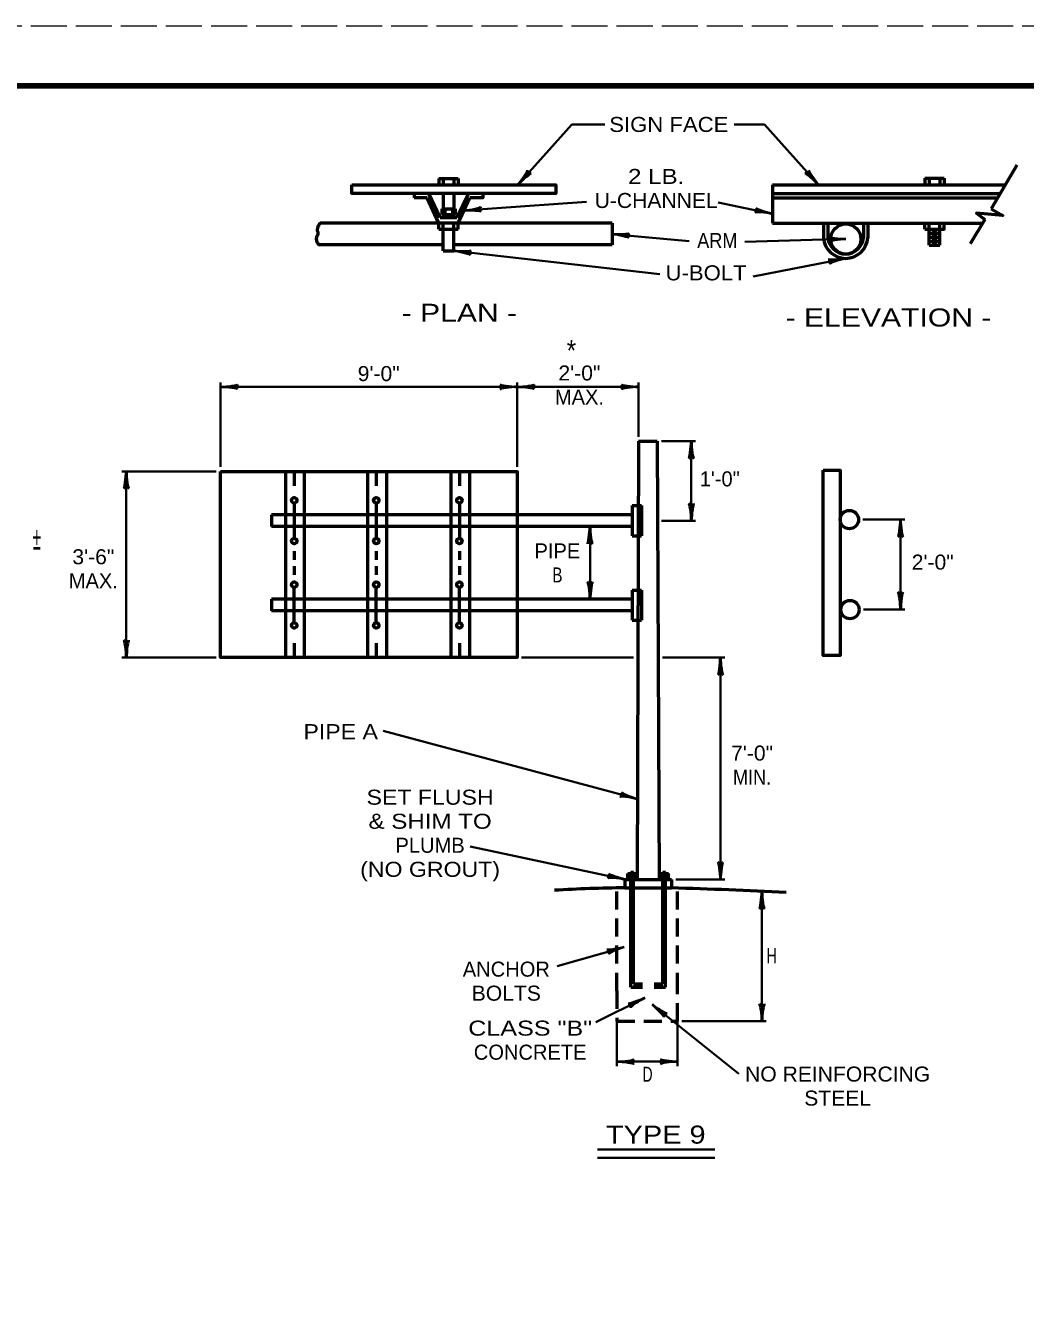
# Model space of a CAD drawing. Extents: x -209 to 471, y -242 to 199.
# Drawn here: x 135.5 to 301.8, y -15.9 to 198.5 of the extents above; entities that cross this region are included whole.
import ezdxf
from ezdxf.enums import TextEntityAlignment as Align

# ---------------------------------------------------------------- set-up
doc = ezdxf.new("R2010")
doc.units = 0
doc.linetypes.add('LONG_DASHED', pattern=[7.5, 6, -1.5])
doc.linetypes.add('MEDIUM_DASHED', pattern=[4.5, 3, -1.5])
doc.layers.add('1', color=7, linetype='Continuous', lineweight=53)
doc.layers.add('61', color=7, linetype='Continuous', lineweight=35)

msp = doc.modelspace()

# ---------------------------------------------------------------- linework, layer by layer
at = {"layer": '1', "lineweight": 35}
for p, q in [((226.391, 182.095), (217.419, 172.072)), ((226.391, 182.095), (231.889, 182.095)), ((253.416, 182.095), (258.453, 182.095)), ((258.453, 182.095), (267.424, 172.072)), ((208.451, 167.785), (228.847, 169.222)), ((259.734, 167.233), (250.725, 169.105)), ((233.092, 163.865), (245.928, 162.668)), ((271.992, 163.035), (255.171, 162.551)), ((206.757, 161.073), (241.015, 157.168)), ((271.959, 159.806), (256.575, 156.817)), ((167.948, 125.1), (167.948, 139.154)), ((217.31, 138.428), (167.948, 138.428)), ((217.31, 125.1), (217.31, 139.154)), ((217.31, 138.428), (237.489, 138.428)), ((237.489, 130.101), (237.489, 139.154)), ((241.339, 129.375), (247.003, 129.375)), ((246.277, 116.162), (246.277, 129.375)), ((167.222, 124.374), (151.528, 124.374)), ((152.254, 124.374), (152.254, 93.388)), ((241.339, 116.162), (247.003, 116.162)), ((274.829, 116.345), (281.821, 116.345)), ((281.095, 116.345), (281.095, 101.369)), ((229.422, 115.194), (229.422, 103.094)), ((274.932, 101.369), (281.821, 101.369)), ((167.222, 93.388), (151.528, 93.388)), ((218.036, 93.388), (236.664, 93.388)), ((241.488, 93.388), (251.857, 93.388)), ((251.131, 93.388), (251.131, 56.472)), ((237.265, 69.859), (195.022, 81.176)), ((235.23, 56.472), (209.49, 61.933)), ((243.698, 56.472), (251.857, 56.472)), ((258.031, 32.869), (258.031, 54.452)), ((235.109, 45.219), (223.937, 42.039)), ((238.523, 36.761), (230.376, 32.726)), ((239.764, 35.675), (254.195, 24.111)), ((233.895, 32.869), (233.895, 25.422)), ((243.999, 32.869), (243.999, 25.422)), ((244.725, 32.869), (258.757, 32.869)), ((233.895, 26.148), (243.999, 26.148)), ((230.65, 11.509), (250.21, 11.509)), ((230.65, 10.143), (250.21, 10.143))]:
    msp.add_line(p, q, dxfattribs=at)
at = {"layer": '1'}
for p, q in [((300.469, 175.307), (296.168, 168.055)), ((204.27, 173.111), (207.483, 173.111)), ((204.27, 173.111), (204.27, 172.072)), ((204.996, 173.111), (204.996, 172.072)), ((206.757, 173.111), (206.757, 172.072)), ((207.483, 173.111), (207.483, 172.072)), ((259.765, 172.072), (259.765, 165.689)), ((259.765, 172.072), (298.549, 172.072)), ((285.12, 173.135), (288.333, 173.135)), ((285.12, 173.135), (285.12, 172.096)), ((285.846, 173.135), (285.846, 172.072)), ((287.607, 173.135), (287.607, 172.096)), ((288.333, 173.135), (288.333, 172.096)), ((200.156, 170.59), (200.156, 169.878)), ((202.334, 169.878), (200.156, 169.878)), ((204.27, 165.691), (202.334, 169.878)), ((204.512, 166.593), (202.576, 170.59)), ((204.996, 170.59), (204.996, 168.035)), ((206.757, 170.59), (206.757, 168.035)), ((207.241, 166.593), (209.177, 170.59)), ((207.483, 165.691), (209.419, 169.878)), ((259.765, 170.59), (297.67, 170.59)), ((259.765, 169.878), (297.249, 169.878)), ((204.754, 168.035), (204.754, 167.085)), ((204.754, 168.035), (206.999, 168.035)), ((205.238, 168.035), (205.238, 167.085)), ((206.515, 168.035), (206.515, 167.085)), ((206.999, 168.035), (206.999, 167.085)), ((233.092, 165.689), (184.493, 165.689)), ((204.27, 164.653), (204.27, 165.691)), ((204.512, 166.593), (207.241, 166.593)), ((204.754, 167.085), (206.999, 167.085)), ((204.996, 167.085), (204.996, 166.593)), ((204.996, 161.073), (204.996, 165.691)), ((206.757, 167.085), (206.757, 166.593)), ((206.757, 161.073), (206.757, 165.691)), ((207.483, 164.653), (207.483, 165.691)), ((233.092, 165.689), (233.092, 162.041)), ((259.765, 165.689), (294.762, 165.689)), ((268.283, 165.681), (268.283, 163.255)), ((269.009, 165.681), (269.009, 163.255)), ((274.908, 165.681), (274.908, 163.255)), ((275.634, 165.681), (275.634, 163.255)), ((285.12, 164.651), (285.12, 165.689)), ((285.846, 164.651), (285.846, 165.689)), ((287.607, 162.015), (287.607, 165.689)), ((295.107, 166.268), (292.703, 162.215)), ((204.27, 164.653), (207.483, 164.653)), ((285.846, 163.993), (287.607, 163.993)), ((285.846, 163.334), (287.607, 163.334)), ((286.33, 164.322), (287.123, 164.322)), ((286.33, 163.665), (287.123, 163.665)), ((286.33, 163.005), (287.123, 163.005)), ((204.996, 162.041), (184.493, 162.041)), ((204.996, 161.073), (206.757, 161.073)), ((233.092, 162.041), (206.757, 162.041)), ((285.846, 162.675), (287.607, 162.675)), ((285.846, 162.015), (287.607, 162.015)), ((286.33, 162.346), (287.123, 162.346)), ((237.489, 129.375), (237.287, 56.472)), ((237.489, 129.375), (240.613, 129.375)), ((240.613, 129.375), (240.915, 56.472)), ((178.757, 124.374), (178.757, 93.388)), ((180.199, 124.374), (180.199, 121.954)), ((181.871, 124.374), (181.871, 93.388)), ((192.416, 124.374), (192.416, 93.388)), ((193.858, 124.374), (193.858, 121.954)), ((195.53, 124.374), (195.53, 93.388)), ((206.247, 124.374), (206.247, 93.388)), ((207.689, 124.374), (207.689, 121.954)), ((209.36, 124.374), (209.36, 93.388)), ((180.199, 119.1), (180.199, 113.223)), ((193.858, 119.1), (193.858, 113.223)), ((207.689, 119.1), (207.689, 113.223)), ((236.43, 118.662), (238.017, 118.662)), ((236.43, 118.662), (236.43, 113.661)), ((238.017, 118.662), (238.017, 113.661)), ((236.43, 117.13), (176.396, 117.13)), ((176.396, 117.13), (176.396, 115.194)), ((236.43, 115.194), (176.396, 115.194)), ((236.43, 113.661), (238.017, 113.661)), ((180.199, 111.114), (180.199, 109.628)), ((193.858, 111.114), (193.858, 109.628)), ((207.689, 111.114), (207.689, 109.628)), ((180.199, 108.611), (180.199, 107.173)), ((193.858, 108.611), (193.858, 107.173)), ((207.689, 108.611), (207.689, 107.173)), ((180.199, 99.187), (180.199, 105.064)), ((193.858, 99.187), (193.858, 105.064)), ((207.689, 99.187), (207.689, 105.064)), ((236.43, 103.094), (176.396, 103.094)), ((176.396, 103.094), (176.396, 101.158)), ((236.43, 104.626), (238.017, 104.626)), ((236.43, 104.626), (236.43, 99.625)), ((238.017, 104.626), (238.017, 99.625)), ((236.43, 101.158), (176.396, 101.158)), ((236.43, 99.625), (238.017, 99.625)), ((180.199, 95.807), (180.199, 93.388)), ((193.858, 95.807), (193.858, 93.388)), ((207.689, 95.807), (207.689, 93.388)), ((235.23, 56.472), (242.972, 56.472)), ((235.23, 56.472), (235.23, 55.063)), ((235.714, 56.472), (235.714, 57.44)), ((235.714, 57.44), (237.166, 57.44)), ((236.125, 57.44), (236.125, 57.513)), ((236.125, 57.513), (236.755, 57.513)), ((236.198, 57.682), (236.682, 57.682)), ((236.198, 57.513), (236.198, 57.682)), ((236.198, 38.568), (236.198, 57.44)), ((236.682, 57.513), (236.682, 57.682)), ((236.682, 39.119), (236.682, 57.44)), ((236.755, 57.44), (236.755, 57.513)), ((237.166, 56.472), (237.166, 57.44)), ((241.036, 57.44), (242.488, 57.44)), ((241.036, 56.472), (241.036, 57.44)), ((241.447, 57.44), (241.447, 57.513)), ((241.447, 57.513), (242.077, 57.513)), ((241.52, 57.682), (242.004, 57.682)), ((241.52, 57.513), (241.52, 57.682)), ((241.52, 39.119), (241.52, 57.44)), ((242.004, 57.513), (242.004, 57.682)), ((242.004, 38.568), (242.004, 57.44)), ((242.077, 57.44), (242.077, 57.513)), ((242.488, 56.472), (242.488, 57.44)), ((242.972, 56.472), (242.972, 55.063)), ((235.23, 55.063), (242.972, 55.063)), ((236.682, 39.119), (238.134, 39.119)), ((240.07, 39.119), (241.52, 39.119)), ((236.198, 38.568), (238.134, 38.568)), ((240.07, 38.568), (242.004, 38.568))]:
    msp.add_line(p, q, dxfattribs=at)
at = {"layer": '1', "linetype": 'MEDIUM_DASHED'}
for p, q in [((233.895, 37.953), (233.895, 55.049)), ((243.999, 37.953), (243.999, 55.03))]:
    msp.add_line(p, q, dxfattribs=at)
at = {"layer": '1'}
for points in [[(189.791, 172.072), (223.747, 172.072), (223.747, 170.59), (189.791, 170.59)], [(167.948, 124.374), (217.31, 124.374), (217.31, 93.388), (167.948, 93.388)], [(268.217, 124.569), (271.058, 124.569), (271.058, 93.704), (268.217, 93.704)]]:
    msp.add_lwpolyline(points, close=True, dxfattribs=at)
for points in [[(211.597, 170.59), (211.597, 169.878), (209.419, 169.878)], [(296.168, 168.055), (298.144, 166.97), (293.717, 167.313), (295.107, 166.268)], [(285.12, 164.651), (288.333, 164.651), (288.333, 165.689)], [(285.846, 163.334), (285.846, 163.993), (285.846, 164.651)], [(285.846, 162.015), (285.846, 162.675), (285.846, 163.334)]]:
    msp.add_lwpolyline(points, dxfattribs=at)
at = {"layer": '1', "linetype": 'MEDIUM_DASHED'}
msp.add_lwpolyline([(233.895, 37.953), (233.895, 32.869), (243.999, 32.869), (243.999, 37.953)], dxfattribs=at)
msp.add_lwpolyline([(233.895, 37.953), (233.895, 32.869), (243.999, 32.869), (243.999, 37.953)], dxfattribs=at)
at = {"layer": '1'}
for centre, radius in [((271.992, 163.035), 2.502), ((180.199, 119.55), 0.45), ((193.858, 119.55), 0.45), ((207.689, 119.55), 0.45), ((272.581, 116.345), 1.523), ((180.199, 112.774), 0.45), ((193.858, 112.774), 0.45), ((207.689, 112.774), 0.45), ((180.199, 105.514), 0.45), ((193.858, 105.514), 0.45), ((207.689, 105.514), 0.45), ((272.684, 101.369), 1.523), ((180.199, 98.738), 0.45), ((193.858, 98.738), 0.45), ((207.689, 98.738), 0.45)]:
    msp.add_circle(centre, radius, dxfattribs=at)
for centre, radius, start, end in [((271.959, 163.491), 3.685, 183.66168, 356.33832), ((271.959, 163.491), 2.959, 184.56187, 355.43813), ((237.095, -169.491), 224.561, 90.47573, 93.46734), ((213.381, -913.582), 969.096, 87.12083, 88.25023)]:
    msp.add_arc(centre, radius, start, end, dxfattribs=at)
at = {"layer": '1', "lineweight": 40}
for centre, major_axis, ratio, start_param, end_param in [((217.941, 173.07), (-1.075, -1.435), 0.122415, 0.8963533, 3.1415927), ((217.941, 173.07), (-1.075, -1.435), 0.122415, 0.8963533, 3.1415927), ((218.324, 172.766), (-1.302, -1.192), 0.07063, 3.1407148, 5.41811), ((218.324, 172.766), (-1.302, -1.192), 0.07063, 3.1407148, 5.41811), ((266.49, 172.701), (1.307, -1.226), 0.122415, 0.8963533, 3.1415927), ((266.49, 172.701), (1.307, -1.226), 0.122415, 0.8963533, 3.1415927), ((266.834, 173.048), (1.041, -1.426), 0.07063, 3.1407148, 5.41811), ((266.834, 173.048), (1.041, -1.426), 0.07063, 3.1407148, 5.41811), ((209.52, 168.137), (-1.77, -0.281), 0.122415, 0.8963533, 3.1415927), ((209.52, 168.137), (-1.77, -0.281), 0.122415, 0.8963533, 3.1415927), ((209.583, 167.653), (-1.764, 0.052), 0.07063, 3.1407148, 5.41811), ((209.583, 167.653), (-1.764, 0.052), 0.07063, 3.1407148, 5.41811), ((258.609, 167.184), (1.78, -0.211), 0.122415, 0.8963533, 3.1415927), ((258.609, 167.184), (1.78, -0.211), 0.122415, 0.8963533, 3.1415927), ((258.68, 167.668), (1.684, -0.529), 0.07063, 3.1407148, 5.41811), ((258.68, 167.668), (1.684, -0.529), 0.07063, 3.1407148, 5.41811), ((234.188, 163.551), (-1.733, 0.338), 0.07063, 3.1407148, 5.41811), ((234.205, 164.039), (-1.792, 0.01), 0.122415, 0.8963533, 3.1415927), ((270.866, 163.214), (1.761, -0.125), 0.07063, 3.1407148, 5.41811), ((270.866, 163.214), (1.761, -0.125), 0.07063, 3.1407148, 5.41811), ((270.909, 162.727), (1.78, 0.207), 0.122415, 0.8963533, 3.1415927), ((270.909, 162.727), (1.78, 0.207), 0.122415, 0.8963533, 3.1415927), ((207.846, 160.736), (-1.725, 0.373), 0.07063, 3.1407148, 5.41811), ((207.846, 160.736), (-1.725, 0.373), 0.07063, 3.1407148, 5.41811), ((207.872, 161.224), (-1.792, 0.047), 0.122415, 0.8963533, 3.1415927), ((207.872, 161.224), (-1.792, 0.047), 0.122415, 0.8963533, 3.1415927), ((270.818, 159.8), (1.758, 0.163), 0.07063, 3.1407148, 5.41811), ((270.818, 159.8), (1.758, 0.163), 0.07063, 3.1407148, 5.41811), ((270.94, 159.327), (1.723, 0.494), 0.122415, 0.8963533, 3.1415927), ((270.94, 159.327), (1.723, 0.494), 0.122415, 0.8963533, 3.1415927), ((169.039, 138.704), (-1.786, -0.156), 0.122415, 0.8963533, 3.1415927), ((169.039, 138.704), (-1.786, -0.156), 0.122415, 0.8963533, 3.1415927), ((169.069, 138.216), (-1.756, 0.176), 0.07063, 3.1407148, 5.41811), ((169.069, 138.216), (-1.756, 0.176), 0.07063, 3.1407148, 5.41811), ((216.219, 138.151), (1.786, 0.156), 0.122415, 0.8963533, 3.1415927), ((216.219, 138.151), (1.786, 0.156), 0.122415, 0.8963533, 3.1415927), ((216.189, 138.639), (1.756, -0.176), 0.07063, 3.1407148, 5.41811), ((216.189, 138.639), (1.756, -0.176), 0.07063, 3.1407148, 5.41811), ((218.401, 138.704), (-1.786, -0.156), 0.122415, 0.8963533, 3.1415927), ((218.401, 138.704), (-1.786, -0.156), 0.122415, 0.8963533, 3.1415927), ((218.431, 138.216), (-1.756, 0.176), 0.07063, 3.1407148, 5.41811), ((218.431, 138.216), (-1.756, 0.176), 0.07063, 3.1407148, 5.41811), ((236.398, 138.151), (1.786, 0.156), 0.122415, 0.8963533, 3.1415927), ((236.398, 138.151), (1.786, 0.156), 0.122415, 0.8963533, 3.1415927), ((236.368, 138.639), (1.756, -0.176), 0.07063, 3.1407148, 5.41811), ((236.368, 138.639), (1.756, -0.176), 0.07063, 3.1407148, 5.41811), ((246.066, 128.254), (0.176, 1.756), 0.07063, 3.1407148, 5.41811), ((246.554, 128.284), (-0.156, 1.786), 0.122415, 0.8963533, 3.1415927), ((152.043, 123.253), (0.176, 1.756), 0.07063, 3.1407148, 5.41811), ((152.043, 123.253), (0.176, 1.756), 0.07063, 3.1407148, 5.41811), ((152.531, 123.282), (-0.156, 1.786), 0.122415, 0.8963533, 3.1415927), ((152.531, 123.282), (-0.156, 1.786), 0.122415, 0.8963533, 3.1415927), ((246.001, 117.253), (0.156, -1.786), 0.122415, 0.8963533, 3.1415927), ((246.489, 117.282), (-0.176, -1.756), 0.07063, 3.1407148, 5.41811), ((280.884, 115.225), (0.176, 1.756), 0.07063, 3.1407148, 5.41811), ((281.371, 115.254), (-0.156, 1.786), 0.122415, 0.8963533, 3.1415927), ((229.21, 114.073), (0.176, 1.756), 0.07063, 3.1407148, 5.41811), ((229.698, 114.102), (-0.156, 1.786), 0.122415, 0.8963533, 3.1415927), ((229.146, 104.185), (0.156, -1.786), 0.122415, 0.8963533, 3.1415927), ((229.634, 104.214), (-0.176, -1.756), 0.07063, 3.1407148, 5.41811), ((280.819, 102.461), (0.156, -1.786), 0.122415, 0.8963533, 3.1415927), ((281.307, 102.49), (-0.176, -1.756), 0.07063, 3.1407148, 5.41811), ((151.978, 94.479), (0.156, -1.786), 0.122415, 0.8963533, 3.1415927), ((151.978, 94.479), (0.156, -1.786), 0.122415, 0.8963533, 3.1415927), ((152.466, 94.508), (-0.176, -1.756), 0.07063, 3.1407148, 5.41811), ((152.466, 94.508), (-0.176, -1.756), 0.07063, 3.1407148, 5.41811), ((250.92, 92.267), (0.176, 1.756), 0.07063, 3.1407148, 5.41811), ((251.408, 92.296), (-0.156, 1.786), 0.122415, 0.8963533, 3.1415927), ((236.237, 70.353), (1.651, -0.624), 0.07063, 3.1407148, 5.41811), ((236.237, 70.353), (1.651, -0.624), 0.07063, 3.1407148, 5.41811), ((236.139, 69.874), (1.765, -0.311), 0.122415, 0.8963533, 3.1415927), ((236.139, 69.874), (1.765, -0.311), 0.122415, 0.8963533, 3.1415927), ((250.855, 57.564), (0.156, -1.786), 0.122415, 0.8963533, 3.1415927), ((250.855, 57.564), (0.156, -1.786), 0.122415, 0.8963533, 3.1415927), ((251.343, 57.593), (-0.176, -1.756), 0.07063, 3.1407148, 5.41811), ((251.343, 57.593), (-0.176, -1.756), 0.07063, 3.1407148, 5.41811), ((234.105, 56.429), (1.779, -0.218), 0.122415, 0.8963533, 3.1415927), ((234.105, 56.429), (1.779, -0.218), 0.122415, 0.8963533, 3.1415927), ((234.178, 56.912), (1.682, -0.536), 0.07063, 3.1407148, 5.41811), ((234.178, 56.912), (1.682, -0.536), 0.07063, 3.1407148, 5.41811), ((257.819, 53.331), (0.176, 1.756), 0.07063, 3.1407148, 5.41811), ((257.819, 53.331), (0.176, 1.756), 0.07063, 3.1407148, 5.41811), ((258.307, 53.36), (-0.156, 1.786), 0.122415, 0.8963533, 3.1415927), ((258.307, 53.36), (-0.156, 1.786), 0.122415, 0.8963533, 3.1415927), ((233.973, 45.116), (1.737, 0.312), 0.07063, 3.1407148, 5.41811), ((233.973, 45.116), (1.737, 0.312), 0.07063, 3.1407148, 5.41811), ((234.135, 44.655), (1.675, 0.639), 0.122415, 0.8963533, 3.1415927), ((234.135, 44.655), (1.675, 0.639), 0.122415, 0.8963533, 3.1415927), ((237.425, 36.454), (1.652, 0.622), 0.07063, 3.1407148, 5.41811), ((237.668, 36.03), (1.531, 0.932), 0.122415, 0.8963533, 3.1415927), ((240.506, 34.809), (-1.261, 1.235), 0.07063, 3.1407148, 5.41811), ((240.506, 34.809), (-1.261, 1.235), 0.07063, 3.1407148, 5.41811), ((240.788, 35.208), (-1.491, 0.995), 0.122415, 0.8963533, 3.1415927), ((240.788, 35.208), (-1.491, 0.995), 0.122415, 0.8963533, 3.1415927), ((257.754, 33.961), (0.156, -1.786), 0.122415, 0.8963533, 3.1415927), ((257.754, 33.961), (0.156, -1.786), 0.122415, 0.8963533, 3.1415927), ((258.242, 33.99), (-0.176, -1.756), 0.07063, 3.1407148, 5.41811), ((258.242, 33.99), (-0.176, -1.756), 0.07063, 3.1407148, 5.41811), ((234.986, 26.424), (-1.786, -0.156), 0.122415, 0.8963533, 3.1415927), ((234.986, 26.424), (-1.786, -0.156), 0.122415, 0.8963533, 3.1415927), ((235.016, 25.936), (-1.756, 0.176), 0.07063, 3.1407148, 5.41811), ((235.016, 25.936), (-1.756, 0.176), 0.07063, 3.1407148, 5.41811), ((242.907, 25.871), (1.786, 0.156), 0.122415, 0.8963533, 3.1415927), ((242.907, 25.871), (1.786, 0.156), 0.122415, 0.8963533, 3.1415927), ((242.878, 26.359), (1.756, -0.176), 0.07063, 3.1407148, 5.41811), ((242.878, 26.359), (1.756, -0.176), 0.07063, 3.1407148, 5.41811)]:
    msp.add_ellipse(centre, major_axis=major_axis, ratio=ratio, start_param=start_param, end_param=end_param, dxfattribs=at)
at = {"layer": '1'}
msp.add_spline([(184.493, 165.689), (184.206, 165.234), (184.037, 164.435), (184.15, 163.979), (183.922, 163.352), (184.15, 162.269), (184.493, 162.041)], degree=3, dxfattribs=at)
at = {"layer": '61', "linetype": 'LONG_DASHED', "lineweight": 13}
msp.add_line((-208.646, 198.515), (471.374, 198.515), dxfattribs=at)
at = {"layer": '61', "lineweight": 158}
msp.add_lwpolyline([(460.394, 188.515), (-178.646, 188.515), (-178.646, -231.505)], dxfattribs=at)

# ---------------------------------------------------------------- texts
at = {"layer": '1'}
for s, height, width, p in [('SIGN FACE', 2.5, 1.1, (242.536, 180.845)), ('2 LB.', 2.5, 1.2, (240.43, 172.196)), ('U-CHANNEL', 2.5, 1.05, (240.43, 168.196)), ('ARM', 2.5, 0.9, (250.608, 161.535)), ('U-BOLT', 2.5, 1.1, (248.736, 156.152)), ('*', 3.5, 0.85, (226.326, 142.73)), ('9\'-0"', 2.5, 1.05, (194.262, 139.39)), ('2\'-0"', 2.5, 1.05, (227.662, 139.489)), ('+', 3.5, 0.55, (137.376, 111.679)), ('3\'-6"', 2.5, 1.05, (146.775, 108.909)), ('2\'-0"', 2.5, 1.05, (286.451, 108.017)), ('B', 2.5, 0.75, (223.996, 105.881)), ('PIPE A', 2.5, 1.15, (187.934, 79.807)), ('7\'-0"', 2.5, 1.05, (256.393, 76.241)), ('MIN.', 2.5, 0.9, (256.393, 72.241)), ('SET FLUSH', 2.5, 1.15, (202.811, 68.899)), ('& SHIM TO', 2.5, 1.2, (202.811, 64.899)), ('(NO GROUT)', 2.5, 1.15, (202.811, 56.899)), ('H', 2.5, 0.7, (259.636, 42.532)), ('BOLTS', 2.5, 1.05, (215.492, 36.292)), ('CLASS "B"', 2.5, 1.25, (219.463, 30.474)), ('D', 2.5, 0.7, (238.991, 22.795)), ('NO REINFORCING', 2.5, 1.05, (270.625, 22.832)), ('STEEL', 2.5, 1.05, (270.625, 18.832))]:
    msp.add_text(s, height=height, dxfattribs=dict(at, width=width)).set_placement(p, align=Align.CENTER)
for s, width, p in [('- PLAN -', 1.25, (198.073, 149.253)), ('- ELEVATION -', 1.25, (261.953, 148.474)), ('TYPE 9', 1.2, (232.064, 12.505))]:
    msp.add_text(s, height=3, dxfattribs=dict(at, width=width)).set_placement(p)
for s, height, p in [('MAX.', 2.5, (227.662, 135.489)), ('1\'-0"', 2.5, (251.015, 121.87)), ('-', 3.5, (137.376, 110.209)), ('PIPE', 2.5, (223.996, 109.881)), ('MAX.', 2.5, (146.775, 104.909)), ('PLUMB', 2.5, (202.811, 60.899)), ('ANCHOR', 2.5, (215.492, 40.292)), ('CONCRETE', 2.5, (219.463, 26.474))]:
    msp.add_text(s, height=height, dxfattribs=at).set_placement(p, align=Align.CENTER)

doc.saveas('drawing.dxf')
